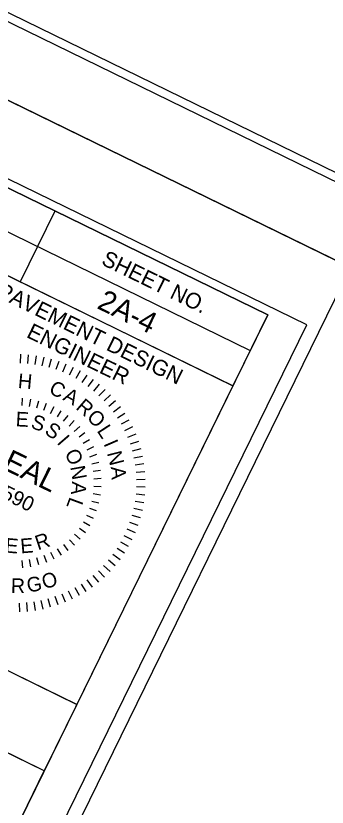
# Model space of a CAD drawing. Extents: x 1518247 to 1523638, y 635234 to 639927.
# Drawn here: x 1521365.4 to 1521464, y 636051.2 to 636302.2 of the extents above; entities that cross this region are included whole.
import ezdxf

# ---------------------------------------------------------------- set-up
doc = ezdxf.new("R2010")
doc.units = 0
for name, color, linetype in [('Default', 7, 'Continuous'), ('DTM TIN Hull White', 7, 'Continuous'), ('Sheet Cutting Line CELL', 7, 'Continuous'), ('Sheet Data Field CELL', 7, 'Continuous'), ('Sheet Plot Border Inside CELL', 7, 'Continuous'), ('Sheet Plot Border Outside CELL', 7, 'Continuous'), ('Sheet Sticker Exception Certification CELL', 7, 'Continuous'), ('Sheet Typical CELL', 7, 'Continuous')]:
    doc.layers.add(name, color=color, linetype=linetype)

msp = doc.modelspace()

# ---------------------------------------------------------------- linework, layer by layer
at = {"layer": 'Default'}
for points in [[(1521471.45, 636222.33), (1519958.68, 636962.19), (1520441.97, 637950.34), (1521954.73, 637210.48)], [(1521178.87, 636118.13), (1521358.57, 636030.25), (1521374.43, 636062.67), (1521194.73, 636150.56)]]:
    msp.add_lwpolyline(points, close=True, dxfattribs=at)
at = {"layer": 'DTM TIN Hull White'}
for p, q in [((1521366.92, 636194.83), (1521366.82, 636192.05)), ((1521369.38, 636194.68), (1521369.12, 636191.9)), ((1521371.83, 636194.38), (1521371.4, 636191.62)), ((1521374.26, 636193.92), (1521373.66, 636191.2)), ((1521376.65, 636193.33), (1521375.9, 636190.65)), ((1521379.01, 636192.58), (1521378.09, 636189.96)), ((1521381.31, 636191.7), (1521380.24, 636189.13)), ((1521383.56, 636190.68), (1521382.34, 636188.18)), ((1521385.75, 636189.53), (1521384.38, 636187.11)), ((1521387.86, 636188.25), (1521386.34, 636185.91)), ((1521389.89, 636186.84), (1521388.23, 636184.6)), ((1521391.82, 636185.31), (1521390.04, 636183.18)), ((1521393.67, 636183.67), (1521391.75, 636181.64)), ((1521367.43, 636180.86), (1521367.27, 636178.54)), ((1521370.02, 636180.55), (1521369.63, 636178.26)), ((1521372.56, 636180), (1521371.96, 636177.76)), ((1521395.41, 636181.92), (1521393.37, 636180.02)), ((1521397.04, 636180.07), (1521394.9, 636178.29)), ((1521375.04, 636179.2), (1521374.22, 636177.03)), ((1521377.43, 636178.17), (1521376.41, 636176.09)), ((1521376.41, 636176.09), (1521377.43, 636178.17)), ((1521398.56, 636178.12), (1521396.31, 636176.47)), ((1521379.71, 636176.91), (1521378.49, 636174.94)), ((1521381.86, 636175.44), (1521380.45, 636173.59)), ((1521399.96, 636176.08), (1521397.61, 636174.58)), ((1521383.85, 636173.77), (1521382.28, 636172.06)), ((1521401.23, 636173.97), (1521398.8, 636172.61)), ((1521385.68, 636171.92), (1521383.95, 636170.37)), ((1521387.31, 636169.89), (1521385.44, 636168.52)), ((1521402.37, 636171.78), (1521399.86, 636170.57)), ((1521403.38, 636169.52), (1521400.8, 636168.46)), ((1521388.75, 636167.72), (1521386.75, 636166.53)), ((1521404.25, 636167.21), (1521401.61, 636166.31)), ((1521389.97, 636165.42), (1521387.86, 636164.43)), ((1521404.97, 636164.85), (1521402.29, 636164.11)), ((1521390.95, 636163.01), (1521388.76, 636162.23)), ((1521405.56, 636162.45), (1521402.84, 636161.88)), ((1521391.71, 636160.52), (1521389.46, 636159.95)), ((1521406, 636160.03), (1521403.24, 636159.61)), ((1521392.22, 636157.97), (1521389.92, 636157.62)), ((1521406.29, 636157.57), (1521403.51, 636157.33)), ((1521392.48, 636155.38), (1521390.16, 636155.25)), ((1521406.43, 636155.11), (1521403.65, 636155.03)), ((1521392.49, 636152.77), (1521390.17, 636152.88)), ((1521406.42, 636152.64), (1521403.64, 636152.73)), ((1521392.24, 636150.18), (1521389.94, 636150.51)), ((1521406.27, 636150.17), (1521403.49, 636150.43)), ((1521391.75, 636147.62), (1521389.49, 636148.17)), ((1521405.97, 636147.72), (1521403.21, 636148.15)), ((1521391.01, 636145.13), (1521388.82, 636145.89)), ((1521405.51, 636145.29), (1521402.79, 636145.89)), ((1521390.04, 636142.71), (1521387.93, 636143.68)), ((1521404.92, 636142.9), (1521402.24, 636143.66)), ((1521385.58, 636139.65), (1521387.47, 636138.29)), ((1521388.84, 636140.4), (1521386.84, 636141.57)), ((1521404.17, 636140.55), (1521401.55, 636141.46)), ((1521385.8, 636136.18), (1521384.05, 636137.72)), ((1521402.27, 636135.99), (1521399.77, 636137.22)), ((1521403.29, 636138.24), (1521400.72, 636139.31)), ((1521382, 636132.63), (1521380.59, 636134.47)), ((1521383.98, 636134.31), (1521382.4, 636136.01)), ((1521401.12, 636133.81), (1521398.7, 636135.18)), ((1521377.59, 636129.87), (1521376.55, 636131.95)), ((1521379.87, 636131.15), (1521378.63, 636133.11)), ((1521399.84, 636131.7), (1521397.5, 636133.21)), ((1521367.62, 636127.12), (1521367.44, 636129.44)), ((1521370.2, 636127.44), (1521369.8, 636129.73)), ((1521372.74, 636128.01), (1521372.12, 636130.25)), ((1521375.21, 636128.83), (1521374.38, 636130.99)), ((1521396.9, 636127.73), (1521394.77, 636129.52)), ((1521398.43, 636129.67), (1521396.19, 636131.32)), ((1521395.26, 636125.88), (1521393.23, 636127.8)), ((1521391.66, 636122.51), (1521389.88, 636124.66)), ((1521393.51, 636124.14), (1521391.61, 636126.18)), ((1521387.67, 636119.6), (1521386.17, 636121.94)), ((1521389.71, 636120.99), (1521388.06, 636123.24)), ((1521383.37, 636117.19), (1521382.15, 636119.69)), ((1521385.56, 636118.33), (1521384.2, 636120.75)), ((1521376.44, 636114.58), (1521375.7, 636117.26)), ((1521378.8, 636115.31), (1521377.9, 636117.94)), ((1521381.11, 636116.18), (1521380.05, 636118.75)), ((1521366.7, 636113.12), (1521366.62, 636115.91)), ((1521369.16, 636113.26), (1521368.92, 636116.04)), ((1521371.61, 636113.56), (1521371.2, 636116.31)), ((1521374.04, 636113.99), (1521373.47, 636116.72))]:
    msp.add_line(p, q, dxfattribs=at)
at = {"layer": 'Sheet Cutting Line CELL'}
for p, q in [((1519958.68, 636962.19), (1521471.45, 636222.33)), ((1521471.45, 636222.33), (1519958.68, 636962.19))]:
    msp.add_line(p, q, dxfattribs=at)
at = {"layer": 'Sheet Plot Border Inside CELL'}
for points in [[(1521940.83, 637192.29), (1520443.78, 637924.46), (1519980.23, 636976.65), (1521477.27, 636244.48)], [(1521457.54, 636204.14), (1519960.5, 636936.31), (1519496.94, 635988.5), (1520993.99, 635256.33)]]:
    msp.add_lwpolyline(points, close=True, dxfattribs=at)
at = {"layer": 'Sheet Plot Border Outside CELL'}
for points in [[(1521954.73, 637210.48), (1520441.97, 637950.34), (1519958.68, 636962.19), (1521471.45, 636222.33)], [(1521471.45, 636222.33), (1519958.68, 636962.19), (1519475.4, 635974.04), (1520988.17, 635234.18)]]:
    msp.add_lwpolyline(points, close=True, dxfattribs=at)
at = {"layer": 'Sheet Sticker Exception Certification CELL'}
for p, q in [((1521205.05, 636171.67), (1521384.75, 636083.78)), ((1521374.43, 636062.67), (1521194.73, 636150.56)), ((1521384.75, 636083.77), (1521374.42, 636062.66))]:
    msp.add_line(p, q, dxfattribs=at)
at = {"layer": 'Sheet Typical CELL'}
for p, q in [((1521259.97, 636283.96), (1521439.68, 636196.07)), ((1521377.8, 636240.25), (1521366.82, 636217.79))]:
    msp.add_line(p, q, dxfattribs=at)
for points in [[(1521928.48, 637195.49), (1520581, 637854.51), (1520119.69, 636911.28), (1521467.16, 636252.26)], [(1521445.2, 636207.34), (1520097.72, 636866.36), (1519636.4, 635923.13), (1520983.88, 635264.11)], [(1521265.49, 636295.23), (1521445.2, 636207.34), (1521434.19, 636184.84), (1521254.48, 636272.73)], [(1521344.36, 636228.77), (1521434.19, 636184.84), (1521384.76, 636083.78), (1521294.93, 636127.71)]]:
    msp.add_lwpolyline(points, close=True, dxfattribs=at)

# ---------------------------------------------------------------- texts
at = {"layer": 'DTM TIN Hull White'}
for s, height, rotation, p in [('H', 4.64, 354.9524, (1521365.95, 636184.15)), ('C', 4.64, 331.2417, (1521375.55, 636182.77)), ('A', 4.64, 331.2417, (1521380.06, 636180.45)), ('R', 4.64, 319.2324, (1521384.17, 636177.67)), ('E', 4.64, 356.8291, (1521365.29, 636172)), ('S', 4.64, 341.5328, (1521369.9, 636171.51)), ('O', 4.64, 316.1756, (1521387.62, 636174.5)), ('S', 4.64, 326.2366, (1521374.23, 636169.82)), ('L', 4.64, 303.0393, (1521390.95, 636170.56)), ('I', 4.64, 310.9403, (1521378.22, 636166.74)), ('I', 4.64, 293.4638, (1521393.12, 636166.5)), ('SEAL', 6.965, 333.8847, (1521355.29, 636161.35)), ('O', 4.64, 295.6441, (1521380.78, 636163.48)), ('N', 4.64, 284.1693, (1521394.25, 636163.51)), ('044590', 4.64, 333.8847, (1521351.2, 636153.85)), ('N', 4.64, 280.3478, (1521382.63, 636159.11)), ('A', 4.64, 274.4018, (1521395.49, 636159.09)), ('A', 4.64, 265.0516, (1521383.24, 636154.58)), ('L', 4.64, 249.7554, (1521382.56, 636149.79)), ('R', 4.64, 18.4496, (1521372.41, 636132.62)), ('E', 4.64, 354.6926, (1521361.87, 636131.98)), ('E', 4.64, 4.6785, (1521367.02, 636131.66)), ('G', 4.64, 8.3265, (1521369.21, 636119.27)), ('O', 4.64, 17.2091, (1521374.46, 636120.23)), ('R', 4.64, 359.5039, (1521363.84, 636119.12))]:
    msp.add_text(s, height=height, rotation=rotation, dxfattribs=at).set_placement(p)
at = {"layer": 'Sheet Data Field CELL'}
msp.add_text('2A-4', height=6.75, rotation=333.9377, dxfattribs=at).set_placement((1521390.82, 636209.56))
at = {"layer": 'Sheet Typical CELL'}
for s, height, p in [('SHEET NO.', 5, (1521392.19, 636223.47)), ('PAVEMENT DESIGN', 5.0001, (1521359.01, 636213.32)), ('ENGINEER', 5, (1521368.49, 636200.39))]:
    msp.add_text(s, height=height, rotation=333.9377, dxfattribs=at).set_placement(p)

doc.saveas('drawing.dxf')
